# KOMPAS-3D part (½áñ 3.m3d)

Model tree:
1. Эскиз:1
2. Операция выдавливания:1
     Расстояние 1 = 20
3. Эскиз:2
4. Операция выдавливания:2
     Расстояние 1 = 400
5. Эскиз:3
6. Вырезать элемент выдавливания:1
     Расстояние 1 = 70
7. Эскиз:4
8. Вырезать элемент выдавливания:2
     Расстояние 1 = 2
9. Эскиз:5
10. Эскиз:11
11. Вырезать элемент выдавливания:7
     Расстояние 1 = 30
12. Операция выдавливания:3
     Расстояние 1 = 16.96
13. Эскиз:13
14. Вырезать элемент выдавливания:9
     Расстояние 1 = 70
15. Эскиз:14
16. Вырезать элемент выдавливания:10
     Расстояние 1 = 80
